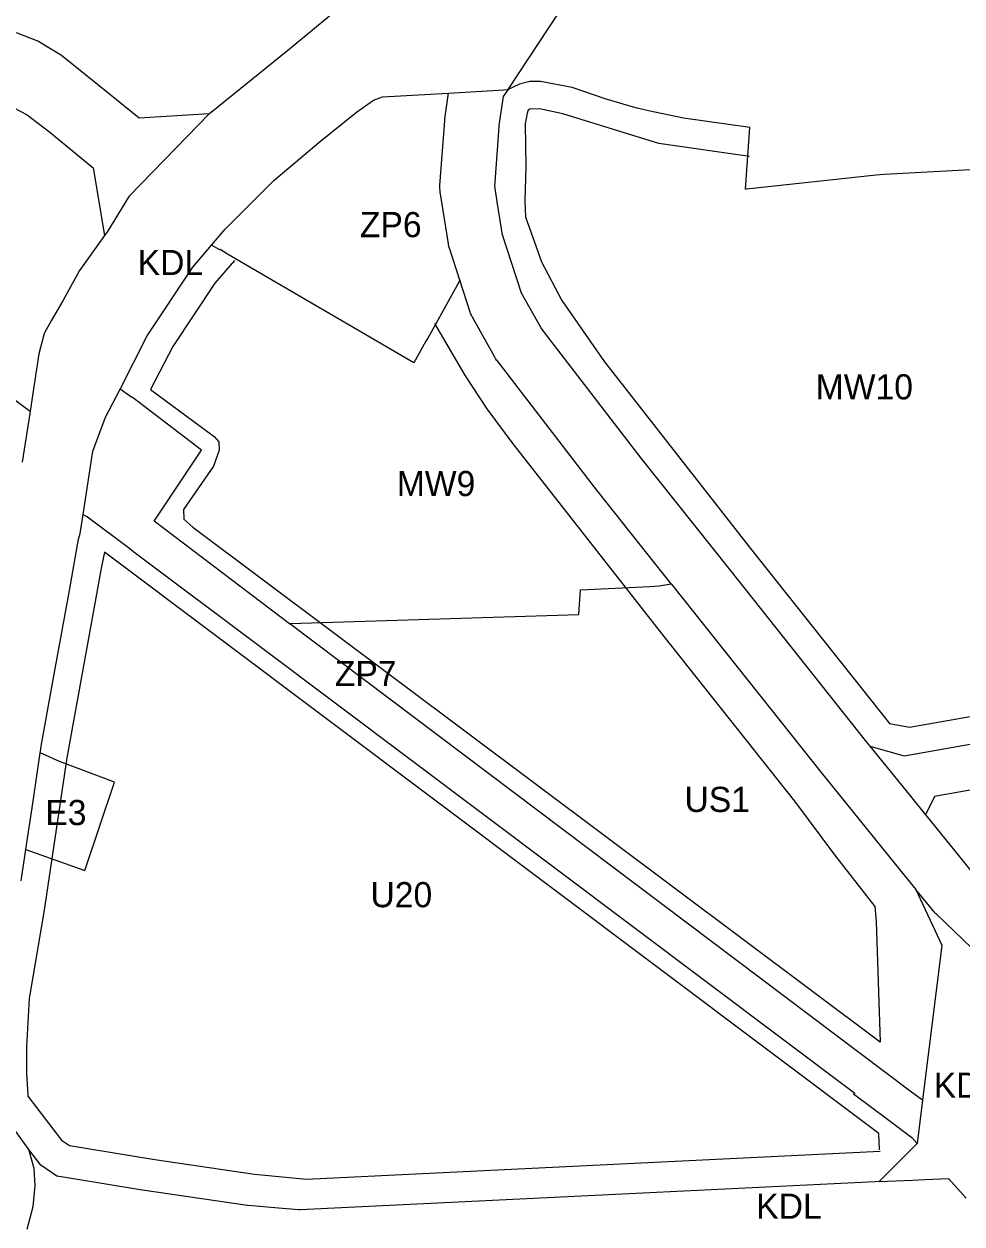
# Model space of a CAD drawing. Extents: x 7428080 to 7432143, y 5545880 to 5549217.
# Drawn here: x 7429133.6 to 7429340.3, y 5547975.6 to 5548240.2 of the extents above; entities that cross this region are included whole.
import ezdxf

# ---------------------------------------------------------------- set-up
doc = ezdxf.new("R2010")
doc.units = 0
for name, color, linetype in [('CZ_L_linie rozgraniczające tereny o różnym przeznaczeniu oraz różnych warunkach ich zabudowy i zagospodarowania', 7, 'Continuous'), ('CZ_L_maksymalne nieprzekraczalne linie zabudowy', 7, 'Continuous'), ('CZ_L_opisy_linie rozgraniczające tereny o różnym przeznaczeniu oraz różnych warunkach ich zabudowy i zagospodarowania', 7, 'Continuous')]:
    doc.layers.add(name, color=color, linetype=linetype)

msp = doc.modelspace()

# ---------------------------------------------------------------- linework, layer by layer
at = {"layer": 'CZ_L_linie rozgraniczające tereny o różnym przeznaczeniu oraz różnych warunkach ich zabudowy i zagospodarowania'}
for p, q in [((7429240.31, 5548225.7), (7429253.81, 5548246.23)), ((7429202.7, 5548243.37), (7429192.13, 5548234.58)), ((7429136.62, 5548236.39), (7429131.95, 5548238.17)), ((7429141.88, 5548233.19), (7429136.62, 5548236.39)), ((7429192.13, 5548234.58), (7429174.45, 5548220.38)), ((7429152.47, 5548224.68), (7429141.88, 5548233.19)), ((7429241.42, 5548226.24), (7429240.31, 5548225.7)), ((7429242.77, 5548226.9), (7429241.42, 5548226.24)), ((7429245.07, 5548227.45), (7429242.77, 5548226.9)), ((7429247.45, 5548227.46), (7429245.07, 5548227.45)), ((7429254.38, 5548226.13), (7429247.45, 5548227.46)), ((7429261.71, 5548223.63), (7429254.38, 5548226.13)), ((7429158.94, 5548219.41), (7429152.47, 5548224.68)), ((7429210.66, 5548223.39), (7429212.6, 5548224.07)), ((7429212.6, 5548224.07), (7429227.16, 5548224.92)), ((7429226.37, 5548219.22), (7429227.16, 5548224.92)), ((7429227.16, 5548224.92), (7429239.38, 5548225.64)), ((7429239.17, 5548224.19), (7429238.28, 5548217.75)), ((7429240.31, 5548225.7), (7429239.17, 5548224.19)), ((7429239.38, 5548225.64), (7429240.31, 5548225.7)), ((7429266.93, 5548222.09), (7429261.71, 5548223.63)), ((7429128.22, 5548223.31), (7429134.26, 5548220.14)), ((7429206.88, 5548220.73), (7429210.66, 5548223.39)), ((7429268.72, 5548221.56), (7429266.93, 5548222.09)), ((7429271.24, 5548221.03), (7429268.72, 5548221.56)), ((7429271.25, 5548221.03), (7429271.24, 5548221.03)), ((7429278.94, 5548219.37), (7429271.25, 5548221.03)), ((7429134.26, 5548220.14), (7429139.28, 5548216.27)), ((7429174.39, 5548220.32), (7429158.94, 5548219.41)), ((7429174.39, 5548220.32), (7429167.07, 5548212.8)), ((7429174.45, 5548220.38), (7429174.39, 5548220.32)), ((7429198.61, 5548214.05), (7429206.88, 5548220.73)), ((7429225.27, 5548204.54), (7429226.32, 5548218.83)), ((7429226.32, 5548218.83), (7429226.33, 5548218.93)), ((7429226.33, 5548218.93), (7429226.37, 5548219.22)), ((7429288.33, 5548218.06), (7429278.94, 5548219.37)), ((7429139.28, 5548216.27), (7429148.82, 5548208.44)), ((7429238.18, 5548216.48), (7429237.29, 5548204.34)), ((7429238.28, 5548217.75), (7429238.18, 5548216.48)), ((7429293.57, 5548217.32), (7429288.33, 5548218.06)), ((7429292.59, 5548203.71), (7429293.57, 5548217.32)), ((7429188.64, 5548205.64), (7429198.61, 5548214.05)), ((7429167.07, 5548212.8), (7429156.85, 5548202.3)), ((7429148.82, 5548208.44), (7429151.36, 5548193.54)), ((7429351.88, 5548208.53), (7429323.27, 5548206.99)), ((7429177.92, 5548194.9), (7429188.64, 5548205.64)), ((7429321.42, 5548206.8), (7429292.85, 5548203.74)), ((7429323.27, 5548206.99), (7429321.42, 5548206.8)), ((7429156.85, 5548202.3), (7429156.66, 5548202)), ((7429225.26, 5548204.24), (7429225.27, 5548204.54)), ((7429225.26, 5548203.85), (7429225.26, 5548204.24)), ((7429225.29, 5548203.46), (7429225.26, 5548203.85)), ((7429225.33, 5548203.17), (7429225.29, 5548203.46)), ((7429227.13, 5548191.66), (7429225.33, 5548203.17)), ((7429237.29, 5548204.34), (7429237.35, 5548203.95)), ((7429237.35, 5548203.95), (7429237.82, 5548200.96)), ((7429292.85, 5548203.74), (7429292.59, 5548203.71)), ((7429156.66, 5548202), (7429151.96, 5548194.39)), ((7429237.82, 5548200.96), (7429238.75, 5548195.01)), ((7429151.96, 5548194.39), (7429151.36, 5548193.54)), ((7429174.95, 5548191.41), (7429177.92, 5548194.9)), ((7429238.75, 5548195.01), (7429238.91, 5548193.99)), ((7429151.36, 5548193.54), (7429145.83, 5548185.78)), ((7429227.15, 5548191.56), (7429227.13, 5548191.66)), ((7429238.91, 5548193.99), (7429243.16, 5548180.86)), ((7429170.77, 5548186.51), (7429174.95, 5548191.41)), ((7429176.77, 5548190.35), (7429174.95, 5548191.41)), ((7429176.83, 5548190.45), (7429176.77, 5548190.35)), ((7429178.44, 5548189.4), (7429176.83, 5548190.45)), ((7429219.52, 5548165.45), (7429178.44, 5548189.4)), ((7429227.23, 5548191.18), (7429227.15, 5548191.56)), ((7429227.33, 5548190.8), (7429227.23, 5548191.18)), ((7429227.35, 5548190.74), (7429227.33, 5548190.8)), ((7429229.65, 5548183.65), (7429227.35, 5548190.74)), ((7429160.74, 5548171.37), (7429170.77, 5548186.51)), ((7429145.83, 5548185.78), (7429142.18, 5548179.15)), ((7429229, 5548182.44), (7429227.81, 5548180.3)), ((7429229.65, 5548183.65), (7429229, 5548182.44)), ((7429231.93, 5548176.6), (7429229.65, 5548183.65)), ((7429142.18, 5548179.15), (7429139.59, 5548174.69)), ((7429227.81, 5548180.3), (7429222.57, 5548170.88)), ((7429243.16, 5548180.86), (7429247.62, 5548172.91)), ((7429232.04, 5548176.29), (7429231.93, 5548176.6)), ((7429232.19, 5548175.93), (7429232.04, 5548176.29)), ((7429232.37, 5548175.58), (7429232.19, 5548175.93)), ((7429139.59, 5548174.69), (7429138.09, 5548172.03)), ((7429232.41, 5548175.52), (7429232.37, 5548175.58)), ((7429237.37, 5548166.66), (7429232.41, 5548175.52)), ((7429137.9, 5548171.31), (7429136.85, 5548167.43)), ((7429138.09, 5548172.03), (7429137.9, 5548171.31)), ((7429154.76, 5548159.67), (7429160.74, 5548171.37)), ((7429222.57, 5548170.88), (7429222.16, 5548170.19)), ((7429247.62, 5548172.91), (7429248.24, 5548172.1)), ((7429248.24, 5548172.1), (7429253.39, 5548165.43)), ((7429222.16, 5548170.19), (7429219.52, 5548165.45)), ((7429136.85, 5548167.43), (7429135.46, 5548158.26)), ((7429237.53, 5548166.39), (7429237.37, 5548166.66)), ((7429237.75, 5548166.06), (7429237.53, 5548166.39)), ((7429237.85, 5548165.93), (7429237.75, 5548166.06)), ((7429260.1, 5548137.07), (7429237.85, 5548165.93)), ((7429253.39, 5548165.43), (7429269.58, 5548144.43)), ((7429134.92, 5548154.74), (7429131.28, 5548157.46)), ((7429135.46, 5548158.26), (7429134.92, 5548154.74)), ((7429151.58, 5548153.46), (7429154.76, 5548159.67)), ((7429157.39, 5548157.79), (7429154.76, 5548159.67)), ((7429157.43, 5548157.86), (7429157.39, 5548157.79)), ((7429172.75, 5548146.17), (7429157.43, 5548157.86)), ((7429134.92, 5548154.74), (7429134.43, 5548151.49)), ((7429148.74, 5548145.95), (7429151.58, 5548153.46)), ((7429134.43, 5548151.49), (7429133.18, 5548143.55)), ((7429146.63, 5548132.03), (7429148.74, 5548145.95)), ((7429162.3, 5548130.54), (7429172.75, 5548146.17)), ((7429269.58, 5548144.43), (7429289.14, 5548119.8)), ((7429260.16, 5548137), (7429260.1, 5548137.07)), ((7429276.27, 5548116.71), (7429260.16, 5548137)), ((7429145.98, 5548127.79), (7429146.63, 5548132.03)), ((7429146.63, 5548132.03), (7429147.11, 5548131.74)), ((7429147.11, 5548131.74), (7429147.13, 5548131.73)), ((7429147.13, 5548131.73), (7429147.57, 5548131.48)), ((7429147.57, 5548131.48), (7429156.89, 5548124.48)), ((7429192.14, 5548107.87), (7429162.3, 5548130.54)), ((7429143.59, 5548115.26), (7429145.62, 5548126.54)), ((7429145.62, 5548126.54), (7429145.98, 5548127.79)), ((7429156.89, 5548124.48), (7429157.79, 5548123.81)), ((7429157.79, 5548123.81), (7429185.95, 5548102.65)), ((7429289.14, 5548119.8), (7429319.28, 5548081.85)), ((7429140.27, 5548096.83), (7429143.59, 5548115.26)), ((7429255.88, 5548109.98), (7429256.24, 5548115.41)), ((7429256.24, 5548115.41), (7429271.54, 5548116.17)), ((7429271.54, 5548116.17), (7429273.58, 5548116.25)), ((7429273.58, 5548116.25), (7429276.27, 5548116.71)), ((7429276.27, 5548116.71), (7429309.91, 5548074.36)), ((7429192.28, 5548107.99), (7429255.88, 5548109.98)), ((7429192.16, 5548107.88), (7429192.14, 5548107.87)), ((7429192.16, 5548107.88), (7429192.28, 5548107.99)), ((7429328.88, 5548004.86), (7429192.16, 5548107.88)), ((7429185.95, 5548102.65), (7429316.69, 5548004.45)), ((7429137.41, 5548080.93), (7429140.27, 5548096.83)), ((7429137.2, 5548079.81), (7429137.41, 5548080.93)), ((7429319.28, 5548081.85), (7429320.05, 5548080.91)), ((7429320.05, 5548080.91), (7429328.95, 5548069.92)), ((7429320.05, 5548080.91), (7429320.85, 5548080.68)), ((7429320.85, 5548080.68), (7429327.62, 5548078.82)), ((7429327.62, 5548078.82), (7429347.33, 5548082.28)), ((7429135.62, 5548068.81), (7429137.15, 5548079.45)), ((7429137.15, 5548079.45), (7429137.2, 5548079.81)), ((7429141.4, 5548077.55), (7429137.15, 5548079.45)), ((7429383.33, 5548078.47), (7429334.25, 5548069.83)), ((7429153.55, 5548073.02), (7429141.4, 5548077.55)), ((7429146.99, 5548053.54), (7429153.55, 5548073.02)), ((7429309.91, 5548074.36), (7429309.94, 5548074.32)), ((7429309.94, 5548074.32), (7429325.71, 5548054.85)), ((7429134.01, 5548058.16), (7429135.62, 5548068.81)), ((7429328.95, 5548069.92), (7429328.95, 5548069.92)), ((7429328.95, 5548069.92), (7429332.32, 5548065.77)), ((7429334.25, 5548069.83), (7429332.32, 5548065.77)), ((7429332.32, 5548065.77), (7429332.36, 5548065.71)), ((7429332.36, 5548065.71), (7429338.98, 5548057.54)), ((7429132.96, 5548051.26), (7429134.01, 5548058.16)), ((7429134.01, 5548058.16), (7429146.99, 5548053.54)), ((7429338.98, 5548057.54), (7429343.25, 5548052.27)), ((7429325.71, 5548054.85), (7429330.19, 5548049.33)), ((7429334.17, 5548044.42), (7429330.19, 5548049.33)), ((7429330.19, 5548049.33), (7429335.88, 5548037.07)), ((7429334.22, 5548044.36), (7429334.17, 5548044.42)), ((7429334.48, 5548044.06), (7429334.22, 5548044.36)), ((7429334.68, 5548043.87), (7429334.48, 5548044.06)), ((7429336.61, 5548042.02), (7429334.68, 5548043.87)), ((7429346.57, 5548032.47), (7429336.61, 5548042.02)), ((7429335.88, 5548037.07), (7429331.62, 5548002.9)), ((7429316.69, 5548004.45), (7429316.42, 5548004.29)), ((7429316.42, 5548004.29), (7429323.88, 5547998.7)), ((7429331.62, 5548002.9), (7429328.88, 5548004.86)), ((7429331.62, 5548002.9), (7429330.43, 5547993.35)), ((7429323.88, 5547998.7), (7429329.29, 5547994.62)), ((7429134.67, 5547991.98), (7429131.78, 5547996.01)), ((7429330.43, 5547993.35), (7429322.06, 5547984.92)), ((7429329.29, 5547994.62), (7429330.43, 5547993.35)), ((7429135.86, 5547987.85), (7429134.67, 5547991.98)), ((7429137.33, 5547988.53), (7429134.67, 5547991.98)), ((7429140.86, 5547986.15), (7429137.33, 5547988.53)), ((7429136.02, 5547984.04), (7429135.86, 5547987.85)), ((7429144.92, 5547985.47), (7429140.86, 5547986.15)), ((7429144.93, 5547985.47), (7429144.92, 5547985.47)), ((7429159.18, 5547983.13), (7429144.93, 5547985.47)), ((7429329.42, 5547985.28), (7429332.13, 5547985.41)), ((7429332.13, 5547985.41), (7429337.38, 5547985.6)), ((7429337.38, 5547985.6), (7429341.26, 5547981.26)), ((7429135.63, 5547979.44), (7429136.02, 5547984.04)), ((7429159.2, 5547983.13), (7429159.18, 5547983.13)), ((7429159.23, 5547983.12), (7429159.2, 5547983.13)), ((7429182.87, 5547979.65), (7429159.23, 5547983.12)), ((7429321.23, 5547984.88), (7429233.85, 5547980.6)), ((7429322.06, 5547984.92), (7429321.23, 5547984.88)), ((7429322.06, 5547984.92), (7429329.42, 5547985.28)), ((7429233.85, 5547980.6), (7429194.49, 5547978.67)), ((7429134.31, 5547974.42), (7429135.63, 5547979.44)), ((7429183.01, 5547979.63), (7429182.87, 5547979.65)), ((7429183.02, 5547979.63), (7429183.01, 5547979.63)), ((7429189.71, 5547979.05), (7429183.02, 5547979.63)), ((7429189.72, 5547979.05), (7429189.71, 5547979.05)), ((7429194.16, 5547978.68), (7429189.72, 5547979.05)), ((7429194.31, 5547978.67), (7429194.16, 5547978.68)), ((7429194.49, 5547978.67), (7429194.31, 5547978.67))]:
    msp.add_line(p, q, dxfattribs=at)
at = {"layer": 'CZ_L_maksymalne nieprzekraczalne linie zabudowy'}
for points in [[(7429293.52, 5548210.93), (7429273.54, 5548213.77), (7429252.34, 5548220.38), (7429247.2, 5548221.45), (7429245.11, 5548221.36), (7429244.71, 5548221.13), (7429244.47, 5548220.47), (7429244.03, 5548218.15), (7429244.17, 5548208.68), (7429243.95, 5548201.14), (7429244.11, 5548197.66), (7429247.65, 5548187.7), (7429252.16, 5548179.18), (7429261.51, 5548165.67), (7429293.45, 5548124.9), (7429324.37, 5548085.93), (7429328.8, 5548085.12), (7429380.66, 5548094.24)], [(7429179.96, 5548188.04), (7429175.68, 5548183.03), (7429166.41, 5548169.07), (7429161.44, 5548159.57), (7429175.47, 5548149.18), (7429176.56, 5548148.04), (7429176.64, 5548146.17), (7429175.37, 5548142.63), (7429168.73, 5548133.12), (7429168.82, 5548130.98), (7429170.77, 5548129.21), (7429322.33, 5548015.73)], [(7429322.4, 5548015.68), (7429321.47, 5548042.31), (7429321.17, 5548045.57), (7429312.51, 5548056.71), (7429303.51, 5548068.81), (7429274.7, 5548105.12), (7429241.4, 5548147.56), (7429235.65, 5548155.28), (7429230.92, 5548162.6), (7429224.17, 5548174.1)], [(7429322.12, 5547991.9), (7429321.97, 5547995.52), (7429151.33, 5548123.73), (7429150.64, 5548120.54), (7429143.06, 5548078.37), (7429138.05, 5548044.77), (7429134.72, 5548025.31), (7429134.13, 5548014.69), (7429134.14, 5548008.85), (7429134.47, 5548004.02)], [(7429134.41, 5548004.06), (7429134.43, 5548003.77), (7429141.84, 5547994.1), (7429143.63, 5547992.87), (7429162.41, 5547989.77), (7429184.41, 5547986.54), (7429195.87, 5547985.46), (7429322.27, 5547991.61)]]:
    msp.add_lwpolyline(points, dxfattribs=at)

# ---------------------------------------------------------------- texts
at = {"layer": 'CZ_L_opisy_linie rozgraniczające tereny o różnym przeznaczeniu oraz różnych warunkach ich zabudowy i zagospodarowania'}
for s, p in [('ZP6', (7429207.62, 5548193.15)), ('KDL', (7429158.64, 5548184.79)), ('MW10', (7429308.09, 5548157.39)), ('MW9', (7429215.75, 5548136.06)), ('ZP7', (7429202.09, 5548094.19)), ('US1', (7429279.17, 5548066.42)), ('E3', (7429138.28, 5548063.53)), ('U20', (7429209.96, 5548045.42)), ('KDL', (7429334.12, 5548003.4)), ('KDL', (7429294.99, 5547976.74))]:
    msp.add_text(s, height=5.549, dxfattribs=at).set_placement(p)

doc.saveas('drawing.dxf')
